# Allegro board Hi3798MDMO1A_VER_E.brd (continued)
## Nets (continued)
NF_DQ1_EMMC_D1: R12.2 U1.R22 U19.30 U22.H4
NF_DQ2_EMMC_D2: R29.2 U1.R21 U19.31 U22.H5
NF_DQ3_EMMC_D3: R58.2 U1.T21 U19.32 U22.J2
NF_DQ4_EMMC_D4: R176.2 U1.T20 U19.41 U22.J3
NF_DQ5_EMMC_D5: R177.2 U1.U22 U19.42 U22.J4
NF_DQ6_EMMC_D6: R188.2 U1.U23 U19.43 U22.J5
NF_DQ7_EMMC_D7_BOOT_SEL0: R82.1 R202.2 U1.U21 U19.44 U22.J6
NF_RDY0_EMMC_RST: C115.1 R203.2 U1.M21 U19.7 U22.U5
NF_REN_EMMC_CLK: R65.1 U19.8 U22.W6
NF_WEN_EMMC_DET: R56.2 U1.P21 U19.18
NF_WP: R89.1 R215.2 U19.19
PWR_OFF/ON: R44.1 R51.1 U1.J23
RECOVERY: C42.2 R47.2 S1.2 U1.J22
RF0: C64.1 L1.2 U7.3
RF1: C50.1 L7.2 U2.7 U7.2
RFF0: C61.1 J5.1 L1.1
RFF1: C60.1 J4.1 L7.1
RX+_PHY0: R63.1 U1.D5 U8.3 U8.6
RX-_PHY0: R64.1 U1.C5 U8.4 U8.5
SDIO0_CARD_DETECT: J21.9 R155.2 U1.F1
SDIO0_CCLK_OUT: J21.5 R5.1
SDIO0_CCMD: J21.3 R153.2 U1.E2
SDIO0_CDATA0: J21.7 R152.2 U1.D3
SDIO0_CDATA1: J21.8 R151.2 U1.C2
SDIO0_CDATA2: J21.1 R156.2 U1.F2
SDIO0_CDATA3: J21.2 R154.2 U1.E1
SDIO0_CWPR: R25.2 U1.C1
SDIO0_PWREN: R76.1 R149.1 U1.F3
SDIO_3318: C22.2 R151.1 R152.1 R153.1 R154.1 R156.1 U1.G5
SPDIF_OUT_BOOT_SEL1: R83.1 U1.A20
STANDBY_PWROFF: R35.1 R73.1 R81.1 R88.1 R98.1 U1.AB23
TX+_PHY0: R59.1 U1.B4 U8.1 U8.8
TX-_PHY0: R62.1 U1.A4 U8.2 U8.7
UART0_RXD: J18.2 R136.2 U1.AA22
UART0_TXD: J18.3 R135.2 U1.AA23
USB0_DM: C95.1 D6.1 J12.2 U1.A6
USB0_DP: C92.1 D1.1 J12.3 U1.B6
USB01_1V1: C334.1 C336.1 LB31.2 U1.G11
USB01_3V3: C10.1 C182.1 LB20.2 U1.D7
USB1_DM: J2.4 U1.B7 U2.4 U7.7
USB1_DP: J2.3 U1.C7 U2.2 U7.6
USB3_DM: J13.2 U1.AC18
USB3_DP: J13.3 U1.AB18
USB3_RXN: J13.5 U1.AB20
USB3_RXP: J13.6 U1.AC20
USB3_TXN: C77.2 U1.AA19
USB3_TXP: C81.2 U1.Y19
USB_BOOT: C89.1 R40.1 S2.1 S2.2
VDAC_3V3: C9.1 C85.1 LB14.2 U1.E20 U1.F19 U1.G19
XIN: C364.1 R1.2 U1.W23 X2.1
XOUT: R1.1 R14.1 U1.W22
$4N774: C43.1 C71.1 R7.2 R21.1
$4N775: C76.1 R53.1 R70.1 R99.2 U11.6
$4N777: L2.1 U11.3
$4N782: C8.1 R73.2 U11.1
$4N811: C82.1 R13.2 R101.1 R110.1 U13.6
$4N812: C45.1 C72.1 R23.1 R102.2
$4N813: R102.1 R110.2
$4N814: L3.1 U13.3
$4N818: C5.1 R81.2 U13.1
$4N881: C84.1 R10.1 R52.1 U15.5
$4N882: L4.1 U15.3
$4N883: C30.1 R6.2 R35.2 U15.1
$4N953: R100.1 R105.1 U14.5
$4N955: D4.1 R95.1 U14.1
$4N956: C83.2 R104.1
$4N957: C24.1 C83.1 U14.6
$4N958: R4.2 U14.7
$4N975: C44.1 U14.8
$4N980: C65.1 R95.2
$4N983: C65.2 L5.1 U14.3
$4N998: R7.1 R70.2
$5N541: Q4.3 R118.2 R144.2
$5N542: C6.2 Q13.1 Q14.1 R118.1
$5N549: Q4.1 R98.2
$6N188: C365.1 R14.2 X2.3
$6N1407: R173.1 U1.E6
$6N2001: R61.2 U1.Y17
$6N2177: R43.1 R85.1 U1.L19
$6N2315: R5.2 U1.E3
$6N2392: R65.2 U1.N23
$7N1408: C250.2 U1.G17
$7N1630: R40.2 U1.H21
$7N1639: R18.2 R87.2 U1.D8
$7N1763: R32.2 U1.F20
$8N1506: R45.1 U1.W16
$8N1514: R36.2 U1.AA7
$8N1515: R37.2 U1.AB7
$9N2352: C255.2 U1.T19
$11N1282: R46.2 U3.L8
$12N1565: R71.2 U6.L8
$13N604: C123.1 C124.1 U22.K2
$13N728: R68.1 U19.39
$13N772: R80.2 U19.38
$14N447: R15.1 U10.3
$14N448: R41.2 U10.4
$14N488: C29.1 C52.1 J12.1 LB2.1 U10.5
$14N520: R11.1 U12.3
$14N521: R42.2 U12.4
$14N524: C38.1 C75.1 J13.1 LB3.1 U12.5
$14N708: C77.1 J13.8
$14N709: C81.1 J13.9
$15N771: C47.1 C177.1 D3.3 R178.1
$15N777: C73.2 Q15.1 R77.2 R267.1
$15N781: Q5.1 R76.2
$15N783: Q5.3 R267.2
$15N941: Q2.1 R31.2
$15N943: Q1.1 R22.2
$15N992: LED1.3 Q1.3 R2.2
$15N993: LED1.1 Q2.3 R34.2
$16N996: C363.1 R66.1 R90.2 R229.1 U5.5
$16N997: C33.2 U5.6
$16N998: C32.1 U5.7
$16N999: C32.2 U5.8
$16N1080: R49.2 R57.1 R91.2
$16N1087: C351.2 R193.1
$16N1088: C55.1 R27.2 U5.2
$16N1091: C317.1 R19.1 R27.1 R193.2
$16N1106: C55.2 R19.2 R74.2 R146.1 U5.3
$16N1113: C350.1 R194.2
$16N1114: C316.1 R20.2 R28.2 R194.1
$16N1117: C54.2 R28.1 U5.13
$16N1132: C54.1 R20.1 R72.1 R145.1 U5.12
$16N1141: R49.1 U5.11
$17N163: C154.1 C297.1 T2.7
$17N165: J25.9 R67.1
$17N167: R59.2 T2.1
$17N168: R63.2 T2.6
$17N169: R62.2 T2.3
$17N170: J25.11 R79.1
$17N171: J25.7 J25.8 R270.2
$17N172: R271.2 T2.15
$17N173: R269.2 T2.10
$17N175: J25.6 T2.9
$17N176: J25.3 T2.11
$17N177: C23.1 R269.1 R270.1 R271.1 R272.1
$17N178: J25.1 T2.16
$17N179: J25.2 T2.14
$17N180: J25.4 J25.5 R272.2
$17N182: R64.2 T2.8
$17N184: C153.1 C307.1 T2.2
$19N506: D19.1 R268.1

Pads without a net: ID1 1; ID2 1; ID3 1; ID4 1; ID5 1; ID6 1; J2 1 6 8 11; J26 14; J34 6; M20 1; M21 1; M22 1; M23 1; T2 4 5 12 13; U1 A8 A9 A11 A12 AA21 AB8 AC8 B9 B11 B12 C9 C10 C11 C12 G21 J21 K20 K21 L22 L23 Y22; U2 3; U3 J1 J9 L1 L9; U6 J1 J9 L1 L9; U7 4 9 10; U11 5; U13 5; U19 3 4 5 6 10 11 14 15 20 21 22 26 27 28 33 35 40 45 46 47; U22 1 2 A4 A6 A9 A11 AA1 AA2 AA7 AA8 AA9 AA10 AA11 AA12 AA13 AA14 AE1 AE14 AG2 AG13 AH4 AH6 AH9 AH11 B2 B13 D1 D14 H1 H2 H6 H7 H8 H9 H10 H11 H12 H13 H14 J1 J7 J8 J9 J10 J11 J12 J13 J14 K1 K3 K5 K7 K8 K9 K10 K11 K12 K13 K14 L1 L2 L3 L4 L12 L13 L14 M1 M2 M3 M5 M8 M9 M10 M12 M13 M14 N1 N2 N3 N10 N12 N13 N14 P1 P2 P3 P10 P12 P13 P14 R1 R2 R3 R5 R12 R13 R14 T1 T2 T3 T5 T12 T13 T14 U1 U2 U3 U6 U7 U10 U12 U13 U14 V1 V2 V3 V12 V13 V14 W1 W2 W3 W7 W8 W9 W10 W11 W12 W13 W14 Y1 Y3 Y6 Y7 Y8 Y9 Y10 Y11 Y12 Y13 Y14

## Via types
v1: diameter 0.508, hole 0.254, TOP to BOTTOM, 880 vias
v2: diameter 0.457, hole 0.203, TOP to BOTTOM, 450 vias

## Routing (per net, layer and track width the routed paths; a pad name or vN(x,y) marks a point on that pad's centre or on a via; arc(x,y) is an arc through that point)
1V1_CORE: length 12.3
  TOP w0.508: v1(70.2,10.33) R101.2 C82.2
  BOTTOM w0.381: 66.67,19.15 66.18,18.66 66.18,16.31 67.38,15.11 67.38,13.36 69.45,11.29 69.45,11.09 v1(70.2,10.33)
  vias: v1(66.74,21.13) v1(66.74,20.42) v1(66.74,19.71) v1(67.47,21.13) v1(67.47,20.42) v1(67.47,19.71) v1(68.23,21.13) v1(68.23,20.42) v1(68.23,19.71) v2(57.12,38.2) v2(57.12,37.4) v2(57.12,36.6) v2(57.92,37.4) v2(57.92,36.6) v2(58.72,37.4) v2(59.52,39.82) v2(59.52,37.4) v2(60.32,39.8) v2(60.32,39) v2(60.32,37.4) v2(62.56,33.31) v2(62.56,32.73) v2(63.14,33.31) v2(63.14,32.73) v2(63.72,33.31) v2(63.72,32.73) v2(67.12,28.32) v2(67.88,28.7) v2(67.85,27.76)
1V1_CPU: length 11.4
  TOP w0.381: v2(69.69,49.66) 69.69,46.65 70.37,45.97 70.37,44.03 70.62,43.77 70.94,43.77 ; v1(69.99,52.01) 69.99,52.85 R53.2 C76.2
  BOTTOM w0.381: v2(69.69,49.66) 69.69,51.72 v1(69.99,52.01)
  vias: v1(69.76,39.39) v1(69.76,38.65) v1(70.67,39.39) v1(70.67,38.65) v1(71.61,39.39) v1(71.61,38.65) v1(72.55,39.39) v1(72.55,38.65) v2(61.92,40.6) v2(61.92,39) v2(61.92,38.2) v2(62.72,40.6) v2(62.72,39.8) v2(62.72,39) v2(62.72,38.2)
1V5_DDR3: length 63.7
  TOP w0.254: U3.K2 v2(36.52,44.65) ; U3.N1 v2(34.12,44.65) ; U3.R1 v2(32.52,44.65) ; U6.K2 v2(37.32,27.44)
  TOP w0.305: U6.R1 v2(32.92,29.19) ; U3.N9 v2(34.52,38.03) ; U6.C1 v2(42.52,29.19) ; U3.H2 v2(38.11,43.85) ; U6.D2 v2(42.1,27.46) ; U3.K8 v2(36.52,39.05) ; U3.R9 v2(32.92,38.1) ; U6.E9 v2(40.92,21.69) ; U3.F1 v2(40.12,45.63) ; U6.A8 v2(44.69,23.04) ; U3.D9 v2(42.12,38.25) ; U6.G7 v2(39.72,24.25) ; U6.F1 40.12,28.64 v2(40.12,29.19) ; U6.H9 38.52,21.73 38.51,21.72 v2(38.47,21.72) ; U3.D2 v2(41.31,43.85) ; U3.B2 v2(43.72,44.66) ; U6.A1 44.12,28.64 v2(44.12,29.19) ; U6.C9 v2(42.52,21.69) ; U6.R9 v2(32.92,21.69) ; U6.H2 v2(38.9,28.23) ; U6.D9 v2(41.72,21.69) ; U3.A1 v2(44.52,45.46) ; U3.C9 v2(42.92,38.25) ; U6.N9 v2(34.52,21.69) ; U3.G7 v2(39.72,40.65) ; U6.K8 v2(36.51,22.64) ; U6.N1 v2(34.52,29.19) ; U3.E9 v2(41.32,38.25) ; U3.C1 v2(42.52,45.6) ; U3.A8 v2(43.72,39.05) ; U3.H9 v2(38.52,38.11) ; U6.B2 v2(43.7,27.46)
  TOP w0.381: R92.1 C66.1 35.73,18.65 v2(35.49,18.88) ; R33.1 C49.1 35.14,34.88 v2(34.91,35.11) ; v1(26.2,39.8) 24.04,37.64 17.2,37.64 C84.2 R10.2
  BOTTOM w0.305: v2(40.92,21.69) 40.71,21.9 C240.1 ; R24.2 v2(58.77,27.79) ; C213.1 34.52,37.51 v2(34.52,38.03) ; v2(38.47,21.72) 39,22.26 C225.1 ; C239.1 41.95,21.93 v2(41.72,21.69) ; C212.1 36.54,39.08 v2(36.52,39.05) ; C229.1 37.33,27.43 v2(37.32,27.44) ; v2(32.92,38.1) 32.92,37.51 C216.1 ; C231.1 42.86,22.04 v2(42.52,21.69) ; C238.1 44.57,22.92 v2(44.69,23.04)
  BOTTOM w0.381: C220.1 42,38.14 v2(42.12,38.25) ; v2(32.92,29.19) 32.92,29.82 C233.1 ; v2(34.12,44.65) 34.28,44.81 C214.1 ; C202.1 44.62,45.55 v2(44.52,45.46) ; C205.1 43.08,44.66 v2(43.72,44.66) ; v2(36.51,22.64) 36.74,22.4 C226.1 ; v2(41.31,43.85) 41.92,44.46 C204.1 ; v2(41.32,38.25) 41.11,38.05 C221.1 ; C230.1 34.52,29.78 v2(34.52,29.19) ; R78.1 v2(40.1,33.05) ; v2(36.52,44.65) 36.13,44.27 C201.1 ; v2(43.7,27.46) 43.57,27.59 C236.1 ; C223.1 v2(40.1,32.16) ; C211.1 v2(39.72,40.65) ; C219.1 42.89,38.23 v2(42.92,38.25) ; v2(40.12,45.63) 40.12,45.39 C209.1 ; C227.1 34.52,21.11 v2(34.52,21.69) ; v2(42.52,45.6) 42.92,46 C203.1 ; C218.1 44.06,39.39 v2(43.72,39.05) ; C215.1 32.58,44.71 v2(32.52,44.65) ; C234.1 42.71,29 v2(42.52,29.19) ; C237.1 41.94,27.62 v2(42.1,27.46) ; C208.1 v2(37.91,47.45) ; C232.1 38.93,28.2 v2(38.9,28.23) ; C258.1 39.17,24.25 v2(39.72,24.25) ; C228.1 32.92,21.12 v2(32.92,21.69) ; C210.1 38.62,43.34 v2(38.11,43.85) ; v2(44.12,29.19) 44.41,28.89 C235.1 ; R54.1 v2(37.02,47.45) ; v2(38.52,38.11) 38.58,38.04 C206.1
  vias: v1(26.2,41.83) v1(26.2,40.81) v1(26.96,41.83) v1(26.96,40.81) v1(26.96,39.8) v2(38.96,26.04) v2(38.96,25.32) v2(39.59,41.59) v2(40.48,41.59) v2(52.32,31.8) v2(53.12,33.4) v2(53.12,32.6) v2(53.12,31.8) v2(53.92,39.8) v2(53.92,39) v2(53.92,34.2) v2(53.92,31.8) v2(54.06,37.71) v2(54.03,36.47) v2(56.32,34.2) v2(56.32,33.4) v2(58.72,33.4) v2(59.52,33.4)
3V3: length 49
  TOP w0.305: U1.V20 v2(65.12,32.6) U1.W20
  TOP w0.381: R6.1 v1(17.43,39.29) ; v1(79.89,6.02) R135.1 79.89,3.89 79.93,3.86 J18.4 ; R136.1 v1(81.67,6.02)
  TOP w0.508: v1(66.9,60.83) 68.17,62.1 v1(68.93,62.1)
  BOTTOM w0.381: R60.1 69.45,7.64 ; C53.1 75,50.01 v1(75.15,50.16) ; C114.1 17.18,44.88 17.18,39.54 v1(17.43,39.29) ; v1(66.01,11.3) 66.25,11.06 R3.1 ; R105.2 v1(66.9,60.83)
  BOTTOM w0.508: 71.31,8.81 71.74,9.24 71.74,11.57 72.61,12.45 72.61,14.1 70.54,16.16 70.54,19.15 71.33,19.93 71.33,25.4 70.8,25.93 68.13,25.93 67.27,26.79 65.49,26.79 65.29,27 R88.2 65.29,27.96 65.59,28.27 66,28.27 66.28,28.55 66.28,31.16 66.25,31.19
  vias: v1(15.17,46.38) v1(15.17,45.61) v1(15.17,44.85) v1(15.93,46.38) v1(15.93,45.61) v1(15.93,44.85) v1(66.77,11.3) v1(67.53,11.3) v1(67.91,11.94) v1(68.29,11.3) v1(68.93,62.87) v1(69.82,62.87) v1(69.82,62.1) v1(70.27,8.43) v1(70.27,7.54) v1(70.71,62.87) v1(71.03,8.43) v1(71.03,7.54) v1(75.15,50.93) v1(75.15,49.4) v1(75.91,50.93) v1(75.91,50.16) v1(75.91,49.4) v1(84.62,56.56) v1(84.62,55.55) v1(84.62,54.53) v1(85.89,56.56) v1(85.89,55.55) v1(85.89,54.53)
3V3_MOS: length 55.1
  TOP w0.254: v2(58.71,43.79) 58.71,43.81 U1.D12
  TOP w0.305: R44.2 69.6,42.46 v1(70.2,43.06) ; R47.1 v1(69.06,75.82)
  TOP w0.381: v1(51.49,67.04) D19.2 ; v1(63.1,50.52) 64.14,49.47 R83.2 ; J25.12 35.66,76.8 36.38,76.08 36.38,64.53 36.64,64.27 R30.1 37.09,63.79 35.85,62.55 v1(35.85,61.77) ; D9.2 v1(67.29,71.92) ; v1(20.86,63.93) R26.1 21.24,64.7 21.62,65.09 21.62,67.99 20.99,68.63 20.99,75.25 22.55,76.8 J25.10
  BOTTOM w0.254: v1(70.39,25.29) 67.98,25.29 67.01,26.26 64.64,26.26 64.28,26.62 LB18.1
  BOTTOM w0.381: v1(21.3,60.37) 21.3,63.49 v1(20.86,63.93) ; v1(69.06,75.82) 69.06,73.69 v1(67.29,71.92) ; C283.1 v1(70.2,43.06)
  vias: v1(17.11,53.77) v1(17.11,53.01) v1(21.3,59.23) v1(23.28,26.72) v1(72.55,10.71) v1(72.55,9.95) v1(73.06,11.32) v1(73.82,11.32) v2(23.28,25.7) v2(24.16,26.72) v2(24.16,25.7) v2(53.12,43) v2(54.54,41.85) v2(55.13,41.85) v2(56.52,43.02) v2(58.73,43.2) v2(63.52,43) v2(63.52,42.2) v2(64.32,37.4) v2(75.79,43.94) v2(75.79,43.18) v2(76.55,43.94) v2(76.55,43.18)
3V3_MOS_FLASH: length 37
  TOP w0.203: U22.Y4 U22.AA3
  TOP w0.254: v1(92.27,45.09) 92.01,45.34 U19.1 ; U19.37 86.51,28.01 v1(86.52,28.01) ; v2(88.01,38.34) U22.W4 U22.Y4 ; 87.01,35.9 87.04,35.87 U22.N5 ; 87.01,35.9 U22.M6 ; 87.01,35.9 v2(86.97,35.94) ; U19.24 v1(80.51,47.55) ; v2(87.51,40.43) U22.AA5 ; v2(89.06,40.43) 88.51,39.89 U22.AA3 ; U22.K6 87.01,34.5 v2(86.65,34.86) 84.85,34.86 84.49,35.22 84.49,37 84.86,37.37 U22.T10 85.53,37.37 v2(85.54,37.36) 85.54,37.84 U22.U9 ; U19.34 85.01,25.36 v1(84.8,25.15) ; 86.51,45.33 U19.12
  TOP w0.381: v2(86.38,43.4) 86.51,43.53 86.51,45.33 ; v2(87.51,40.43) 87.51,41.2 87.94,41.63 88.65,41.63 89.06,41.22 v2(89.06,40.43) ; R68.2 R80.1 v1(85.82,24.15) ; R58.1 v1(81.57,24.05) ; R29.1 v1(81.57,25.07)
  BOTTOM w0.381: 87.6,44.07 91.25,44.07 v1(92.27,45.09) ; v1(80.51,47.55) 79.98,48.08 79.98,50.16 ; R215.1 84.34,42.16 86.09,42.16 86.38,42.45 C142.1
  vias: v1(77.06,50.93) v1(77.06,50.16) v1(77.82,50.93) v1(77.82,50.16)
3V3_SD:
  vias: v1(13.32,56.08) v1(13.32,55.29)
3V3_WIFI:
  vias: v1(17.31,27.48) v1(18.2,27.48)
5V0: length 14.4
  TOP w0.254: 74.64,56.39 74.64,54.23 74.14,53.72 73.25,53.72 72.23,54.74 v1(67.91,54.74)
  TOP w0.381: R144.1 74.58,18.18 v1(74.58,16.33)
  BOTTOM w0.381: R4.1 66.9,55.75 v1(67.91,54.74)
  vias: v1(73.8,14.4) v1(74.71,14.4) v1(75.47,14.4) v1(77.76,73.33) v1(77.76,71.93) v1(77.76,69.39) v1(78.19,61.06) v1(78.19,60.17) v1(78.65,73.33) v1(78.65,71.93) v1(78.65,69.39) v1(79.08,61.06) v1(79.08,60.17) v1(79.54,73.33) v1(79.54,71.93) v1(79.54,69.39) v1(79.97,61.06) v1(79.97,60.17)
5V0_MOS: length 4.1
  TOP w0.381: R15.2 v1(81.63,69.57) ; 76.52,13.61 76.29,13.84 74.36,13.84 R11.2 ; D20.2 v1(55.91,77.1)
  vias: v1(69.15,66.16) v1(69.15,65.4) v1(76.28,18.89) v1(77.25,18.89) v1(77.25,18.16) v1(77.29,17.32) v1(77.71,13.41) v1(77.71,12.7) v1(78.02,14.05) v1(81.25,74.93) v1(82.01,74.93) v1(82.77,74.93)
5V0_MOS_HDMI: length 14
  TOP w0.254: 52.46,78.17 52.22,78.41 J26.18
  TOP w0.381: U4.5 v1(54.01,73.42) 54.73,73.42 55.15,73.84 D20.1 55.15,75.1 54.53,75.73 R187.2 v1(53.78,76.49) 52.46,77.81 52.46,78.17 ; R186.2 v1(52,76.49)
  BOTTOM w0.381: v1(54.01,73.42) 53.93,73.34 C150.1 ; v1(52,76.49) v1(53.78,76.49)
AVDD11_PLL012: length 0.6
  TOP w0.305: U1.P17 v2(61.92,36.6)
AVDD11_USB3:
  vias: v2(61.92,35)
AVDD33_ADAC: length 0.6
  TOP w0.305: U1.E19 v2(64.32,43.8)
AVDD33_PLL01: length 0.6
  TOP w0.305: v2(64.3,35.8) 63.92,35.42 U1.R19
AVDD33_USB2: length 0.6
  TOP w0.305: v2(64.32,39.8) 63.92,39.4 U1.K19
AVDD33_USB3: length 5.6
  TOP w0.254: U1.W18 63.06,32.25 62.38,32.25 U1.W17
  TOP w0.305: U1.W18 v2(63.52,31.8)
  BOTTOM w0.381: LB18.2 64.28,28.99 C18.1 63.74,29.54 63.74,31.58 v2(63.52,31.8)
GND: length 521.8
  TOP w0.089: U22.Y2 89.26,39.62 90.03,39.62
  TOP w0.127: U1.L3 51.12,38.6 ; U1.G16 U1.E16 ; v2(57.92,46.2) 57.92,46.2 v2(58.72,46.2)
  TOP w0.165: U1.AB6 53.52,29.99 53.93,30.4 53.93,31.01 U1.Y7
  TOP w0.203: 62.59,43.81 63.53,43.81 U1.D19 ; U3.J8 38.11,39.85 38.11,40.55 ; U1.AB4 51.92,29.99 52.33,30.4 52.33,30.78 52.13,30.98 51.54,30.98 U1.Y3 ; 61.84,26.54 61.84,27.08 61.94,27.18 61.94,29.34 62.32,29.72 62.32,30.59 U1.AA17 62.32,30.6 v2(62.72,31) ; v2(51.52,35) 50.95,35 50.55,35.4 U1.R2 ; U1.V10 U1.W11 57.92,32.6 v2(58.72,32.6) ; U6.J8 37.72,23.24 37.33,23.63 37.33,24.18 v2(37.43,24.29) ; v2(50.72,31.8) 50.05,31.8 49.65,31.4 U1.Y1 ; v2(59.52,32.6) 60.3,32.6 ; v2(51.52,33.4) 50.9,33.4 50.5,33.8 U1.U2 ; U1.W21 65.92,31.8 66.72,31.8 U1.Y23 ; v2(60.32,31.8) 60.32,31.15 60.72,30.75 U1.AA15 ; U1.W8 55.52,32.6 v2(56.32,32.6) ; U22.AA4 U22.Y5 U22.AA6
  TOP w0.229: v2(87.47,34.86) 87.52,34.86 U22.K4
  TOP w0.254: v1(85.81,28.01) 86.01,27.8 U19.36 ; U3.T1 v2(31.72,44.65) ; v2(49.92,30.2) U1.AA2 ; v2(86.75,40.46) 87.01,40.19 U22.AA6 ; C140.2 v1(60.59,75.36) ; J26.8 v1(47.22,78.31) ; 57.59,58.46 58.66,57.4 R183.2 ; v1(70.33,46.86) v1(70.33,50.87) ; J26.11 v1(48.72,78.31) ; U19.25 80.51,27.85 v1(80.3,28.07) ; U19.2 91.53,46.4 91.53,45.23 v1(91.39,45.09) ; v1(81.27,47.55) 81.01,47.29 U19.23 ; 50.51,41.91 48.61,41.91 46.07,44.45 46.07,46.23 44.93,47.37 43.4,47.37 ; J26.17 v1(51.72,78.31) ; U6.J2 v2(37.32,28.24) ; 72.73,9.37 74.08,10.71 v1(75.73,10.71) ; v2(88.36,41.04) 88.35,41.04 88.35,40.48 88.01,40.15 U22.AA4 ; U3.J2 v2(38.12,44.65) ; U3.M1 v2(35.72,44.65) ; v1(62.77,60.95) 62.52,60.7 C316.2 ; 61.84,25.1 61.84,26.54 ; U1.Y23 67.56,31.4 v2(67.75,31.59) ; U19.48 v1(92.01,28.07) ; J26.5 v1(45.72,78.31) ; J26.2 v1(44.22,78.31) ; R149.2 v1(30.84,50.56) ; C339.2 v1(63.31,75.36) ; U3.P1 v2(33.32,44.65) ; D9.1 v1(66.33,72.94) ; 85.86,45.36 86.01,45.51 U19.13
  TOP w0.305: U1.M8 55.12,38.25 v2(55.05,38.32) ; v2(60.32,31.8) U1.W15 ; v2(50.72,30.2) 51.12,30.6 ; 51.12,30.6 v2(50.72,31) U1.Y3 v2(50.72,31.8) U1.W3 ; 51.12,30.6 U1.AA3 ; U1.K1 v2(49.01,39.4) ; R9.2 v1(69.79,70.48) C79.2 ; U6.E8 v2(41.32,23.44) U6.D8 ; v1(47.15,73.06) U24.3 U24.8 v1(47.15,76.04) ; C42.1 v1(69.06,76.83) ; U6.B9 43.32,21.81 v2(43.41,21.72) ; U1.C8 v2(55.52,45.4) U1.B8 v2(55.52,46.2) ; v2(67.52,29.4) U1.AC23 ; v2(40.12,21.69) 40.14,21.69 40.12,21.72 U6.F9 ; U1.C15 59.92,44.2 U1.D14 v2(59.52,43.8) ; U1.C15 v2(61.12,45.4) ; U1.C15 U1.D15 U1.E16 v2(61.92,43.8) U1.E17 ; v2(51.52,37.4) U1.N3 U1.N2 ; U3.B3 v2(43.72,43.86) ; U1.AB12 v2(57.92,29.4) U1.AC11 ; v2(50.72,32.6) U1.W3 ; U1.W3 v2(51.52,32.6) U1.V4 ; v2(50.87,28.45) 51.12,28.7 U1.AC3 ; v2(53.12,34.2) U1.U5 v2(52.32,33.4) U1.V4 ; 51.12,45 51.12,45 U1.C3 ; U1.P19 63.92,36.2 v2(64.32,36.6) U1.P20 ; U1.J11 57.52,40.2 v2(57.92,39.8) ; U1.V21 v2(65.12,33.4) U1.U20 ; U6.E2 v2(41.3,28.23) 40.92,28.62 U6.E1 ; U1.K5 v2(52.32,39.8) ; U3.E8 v2(41.32,39.05) ; U1.R20 64.72,35.4 v2(65.12,35) ; U1.V4 v2(51.52,33.4) ; 51.12,38.6 v2(50.72,39) U1.K3 v2(51.52,39.8) ; U3.B9 v2(42.92,39.05) ; U6.T1 v2(31.73,29.03) ; v1(45.58,73.01) v1(45.58,74.62) v1(45.58,76.08) ; v2(38.52,41.01) 38.11,40.61 38.11,40.55 ; U6.D1 v2(41.72,29.19) ; U6.G9 39.32,21.72 39.34,21.69 v2(39.29,21.69) ; U1.G3 51.12,41.8 v2(50.72,41.4) 51.12,41 v2(50.72,40.6) U1.J2 ; U1.H13 v2(58.72,41.4) U1.G12 ; v2(28.67,26.16) 29.09,26.59 C314.2 ; v2(64.32,38.2) U1.L20 ; U1.F21 65.04,42.12 U1.G20 64.72,41.8 v2(65.12,41.4) U1.H20 U1.J20 ; U1.AA15 U1.AA14 v2(59.52,30.2) U1.AA13 ; U1.T1 v2(49.01,34.6) ; U3.G9 v2(39.32,38.11) ; U6.P9 v2(33.72,21.69) ; U1.G13 v2(59.52,41.4) U1.H14 ; v2(50.72,47) U1.A3 v2(50.72,46.2) U1.B3 U1.C3 ; U6.M9 v2(35.32,21.69) ; U1.A1 49.52,46.6 v2(49.92,47) U1.A2 v2(49.92,46.2) ; v2(58.72,32.6) 58.72,32.6 U1.W13 v2(59.52,32.6) ; U1.L11 57.52,38.6 v2(57.92,38.2) ; U1.Y1 v2(49.01,31.4) ; v2(57.92,38.2) U1.M11 ; v2(57.92,38.2) U1.L12 ; v2(57.92,38.2) U1.M12 ; U6.G8 v2(39.72,23.45) ; U1.C6 53.52,45 v2(53.92,44.6) 53.52,44.2 U1.D6 ; U3.A9 v2(43.72,38.25) ; U1.D13 U1.C13 59.12,45.8 v2(58.72,46.2) ; U6.B3 v2(43.7,26.66) ; U3.M9 v2(35.32,38.1) ; U6.B1 v2(43.32,29.19) ; U1.R4 v2(51.52,35) ; U1.Y18 v2(62.72,31) U1.AA18 ; U6.G1 v2(39.32,29.61) ; U3.B1 v2(43.72,45.46) ; U1.L4 v2(52.32,38.2) ; U1.W8 55.12,32.2 v2(54.72,31.8) ; U1.D17 v2(62.72,44.6) U1.C17 ; U3.G8 v2(39.72,39.85) ; U3.G1 v2(39.32,45.63) ; C17.2 v1(70.61,75.06) ; U1.C3 U1.C4 U1.D4 51.72,44 51.72,43.6 U1.E4 ; U1.AA8 v2(55.52,31) U1.Y9 ; U1.P1 v2(49.01,36.2) ; v1(43.98,73.06) U23.3 U23.8 v1(43.98,76.09) ; U1.K11 57.52,39.4 v2(57.92,39) U1.K12 ; U3.T9 v2(32.12,38.1) ; U1.H12 58.32,41 v2(58.72,40.6) ; U3.F9 v2(40.12,38.11) ; U3.E1 40.92,45.07 v2(41.31,45.46) U3.D1 ; v2(49.92,29.4) U1.AC1 v2(49.12,28.6) ; U1.AB10 v2(56.32,30.2) ; U6.A9 v2(44.12,21.69) ; U6.P1 v2(33.72,29.19) ; v2(56.32,32.6) U1.V10 ; U3.E2 v2(41.32,44.66) ; U3.P9 v2(33.32,39.05) ; v2(57.12,31.8) U1.W11 ; U6.M1 v2(35.32,29.19) ; U1.J15 v2(61.12,40.6) 60.72,41 U1.H15 U1.G16 ; v2(49.92,30.2) U1.AB1 v2(49.12,29.4) ; U1.AA20 v2(64.32,31) U1.Y20 U1.W19 ; U1.AC5 v2(52.72,28.45) ; U1.D9 v2(55.52,43.8) ; R51.2 v2(68.87,39.12) ; U1.P5 v2(52.32,36.6) ; U1.AA17 v2(61.92,31) ; U1.AC9 v2(55.92,28.5) ; U6.T9 v2(32.12,21.69) ; U3.D8 v2(42.12,39.05)
  TOP w0.356: U5.10 v1(63.66,67.87) ; U5.14 v1(63.66,70.47) 63.11,70.47 62.49,71.09 v1(62.49,71.8) R145.2 ; U5.4 v1(60.11,68.52) ; U5.1 v1(60.11,70.47) 60.78,70.47 61.4,71.09 v1(61.4,71.8) R146.2
  TOP w0.381: R183.2 59.19,57.04 v1(59.72,56.51) ; D6.2 v1(83.49,59.82) ; v1(66.46,70.55) 66.71,70.3 R57.2 ; 89.71,51.13 J3.1 ; J3.1 92.22,51.13 ; J3.1 90.97,52.38 ; J3.1 90.97,49.87 ; C87.2 R93.2 v1(39.48,18.65) ; J21.14 v1(14.39,48.07) ; J13.4 86.4,17.77 ; C33.1 v1(55.53,66.74) ; v2(39.05,34.88) R55.2 C86.2 ; C59.2 v1(75.28,54.86) ; C363.2 v1(54.77,67.88) ; v1(65.36,7.11) 66.38,8.12 Q1.2 ; R13.1 73.69,11.98 v1(73.82,12.11) ; U11.2 v1(70.33,50.87) 70,51.2 C43.2 69.27,51.46 v1(69.27,52.37) ; C95.2 v1(82.39,59.82) ; R50.2 v1(62.9,57.4) ; R52.2 v1(13.5,38.37) ; C317.2 v1(58.33,60.7) ; v2(68.89,47.62) C72.2 ; 85.86,45.36 85.02,44.52 85.02,42.87 v2(84.92,42.77) ; C112.2 v1(75.35,66.21) ; U1.H3 51.12,41 ; C71.2 v1(67.43,52.32) ; D1.2 v1(83.49,63.91) ; R99.1 v1(74.9,53.09) ; U4.2 v1(49.28,73.42) ; C149.2 v1(54.26,70.27) ; v2(54.72,31.8) U1.Y7 ; C92.2 v1(82.39,63.91) ; R8.1 v1(54.26,71.28) ; C45.2 v1(73.08,15.54) ; v1(76.56,14.37) 76.56,14.6 Q4.2 ; R229.2 v1(56.27,72.05) ; R41.1 v1(84.3,69.57)
  TOP w0.508: v1(65.36,7.11) 65.13,6.88 v1(65.13,5.21) LED1.2 ; U11.2 72.6,50.87 v1(72.62,50.85) ; J13.10 87.35,9.58 ; J13.10 87.35,5.82 ; J13.10 85.47,7.7 ; J12.5 90.79,55.28 ; J12.5 86.88,55.28 ; J12.5 88.84,53.33 ; J12.5 88.84,57.24 ; v1(72.62,50.85) v1(72.62,51.96) ; v1(72.62,50.85) v1(72.62,49.88) ; J12.4 87.51,65.35 ; J12.4 84.74,65.35 ; J12.4 86.13,64.29 ; J12.4 86.13,66.42 ; J12.6 88.84,70.38 ; J12.6 88.84,66.47 ; J12.6 90.79,68.42 ; J12.6 86.88,68.42 ; v1(13.17,57.32) 12.85,57.64 J21.6 10.92,57.64
  TOP w0.635: J26.20 55.47,82.88 ; J26.20 54.28,80.8 ; J26.20 56.66,80.8 ; J26.20 55.47,78.72 ; 73.35,84.4 S1.1 ; S1.1 74.55,83.21 ; S1.1 75.74,84.4 ; S1.1 74.55,85.6 ; 85.58,83.7 J1.3 83.42,82.43 ; 80.72,81.25 J10.3 ; J10.3 79.39,83.18 ; J10.3 80.72,85.11 ; J34.5 66.41,77.65 ; J34.5 65.16,79.25 ; J34.5 65.16,76.05 ; 40.97,78.72 J26.21 ; J26.21 40.97,82.88 ; J26.21 39.78,80.8 ; J26.21 42.16,80.8 ; 89.49,20.84 J13.11 87.35,18.96 ; 77.3,80.2 J1.2 ; J1.2 78.62,82.36 ; J1.2 78.62,78.04 ; J1.2 79.94,80.2 ; 81.49,85.38 J10.2 ; J10.2 85.35,85.38 ; J10.2 83.42,86.71 ; S1.3 75.8,83.35 ; S1.3 77.25,81.9 ; S1.3 75.8,80.46 ; S1.3 74.35,81.9 ; 40.97,84.93 J26.23 ; J26.23 42.16,86.76 ; J26.23 39.78,86.76 ; 68.8,80.46 S1.4 ; S1.4 67.35,81.9 ; S1.4 68.8,83.35 ; 55.47,84.93 J26.22 ; J26.22 56.66,86.76 ; J26.22 54.28,86.76
  GND02 w0.635: J2.12 26.74,8.52 ; J2.12 25.75,7.53 ; J2.12 25.75,9.51 ; D3.2 72.63,3.11 ; D3.2 73.62,2.12 ; D3.2 71.64,2.12 ; D3.2 72.63,1.13 ; 87.35,5.9 J13.10 ; J13.10 87.35,9.5 ; J13.10 85.54,7.7 ; J13.10 89.15,7.7 ; 88.84,66.54 J12.6 ; J12.6 86.96,68.42 ; J12.6 88.84,70.3 ; J12.6 90.72,68.42 ; J10.3 80.72,85.03 ; J10.3 79.46,83.18 ; J10.3 80.72,81.32 ; J10.2 83.42,86.63 ; J10.2 81.57,85.38 ; J10.2 85.28,85.38 ; J12.4 87.44,65.35 ; J12.4 84.82,65.35 ; J12.4 86.13,66.34 ; J12.4 86.13,64.36 ; J3.1 90.97,52.31 ; J3.1 90.97,49.94 ; J3.1 92.15,51.13 ; J3.1 89.78,51.13 ; 87.35,19.04 J13.11 ; J13.11 89.15,20.84 ; J13.11 87.35,22.64 ; J13.11 85.54,20.84 ; S1.3 77.17,81.9 ; S1.3 75.8,83.28 ; S1.3 74.43,81.9 ; S1.3 75.8,80.53 ; 77.38,80.2 J1.2 ; J1.2 78.62,82.28 ; J1.2 78.62,78.12 ; J1.2 79.87,80.2 ; 21.76,8.52 J2.10 ; J2.10 22.75,9.51 ; J2.10 22.75,7.53 ; J2.9 17.47,9.51 ; J2.9 17.47,7.53 ; J2.9 18.46,8.52 ; 86.96,55.28 J12.5 ; J12.5 88.84,53.4 ; J12.5 90.72,55.28 ; J12.5 88.84,57.16 ; 84.83,14.27 J13.7 82.87,14.27 ; J13.4 86.33,17.77 ; J13.4 85.35,18.75 ; J13.4 85.35,16.79 ; 65.13,1 LED1.2 ; LED1.2 65.13,3.24 ; LED1.2 64.02,2.12 ; LED1.2 66.25,2.12 ; 55.47,85.01 J26.22 ; J26.22 54.35,86.76 ; J26.22 56.59,86.76 ; 83.42,82.5 J1.3 85.51,83.7 ; 68.8,80.53 S1.4 ; S1.4 67.43,81.9 ; S1.4 68.8,83.28 ; S1.4 70.17,81.9 ; J26.20 55.47,82.81 ; J26.20 55.47,78.79 ; J26.20 56.59,80.8 ; J26.20 54.35,80.8 ; J18.1 84.41,2.24 ; J18.1 83.68,3.17 ; J18.1 83.68,1.32 ; 65.16,76.13 J34.5 ; J34.5 66.33,77.65 ; J34.5 65.16,79.18 ; J26.21 40.97,82.81 ; J26.21 39.85,80.8 ; J26.21 42.09,80.8 ; J26.21 40.97,78.79 ; J2.7 14.47,9.51 ; J2.7 13.48,8.52 ; J2.7 14.47,7.53 ; 39.85,86.76 J26.23 ; J26.23 42.09,86.76 ; J26.23 40.97,85.01 ; S1.1 75.67,84.4 ; S1.1 74.55,83.29 ; S1.1 74.55,85.52 ; S1.1 73.43,84.4 ; 23.08,34.4 J2.2 23.08,36.64
  BOTTOM w0.127: 61.67,37.73 62.39,37.73 v2(62.72,37.4) ; 54.34,46.05 53.96,45.66 ; 61.83,41.09 61.45,40.71 ; 67.75,41.4 67.78,41.37
  BOTTOM w0.254: v2(65.12,41.4) 65.17,41.35 67.7,41.35 ; C53.2 74.14,51.44 ; R48.2 67.42,10.54 v1(66.96,10.08)
  BOTTOM w0.305: C238.2 43.41,21.99 v2(43.41,21.72) ; C212.2 36.54,40.64 36.17,41.01 v2(36.17,41.2) ; C229.2 37.43,25.94 v2(37.43,25.47) ; C231.2 C239.2 41.62,23.15 v2(41.32,23.44) 41.02,23.15 C240.2 40.03,23.15 v2(39.72,23.45) 39.65,23.37 C258.2 ; R61.1 63,28.77 v2(63.43,28.34) ; R71.1 v2(36.59,25.44) ; v2(36.17,41.91) 36.03,42.04 R46.1 ; C8.2 70.2,53.34 ; C225.2 39.82,21.99 v2(40.12,21.69) ; C233.2 32.88,30.77 v2(33.34,31.22) ; C313.2 31.03,44.41 31.25,44.64 31.7,44.64 v2(31.72,44.65) ; C89.2 v1(79.26,43.43)
  BOTTOM w0.381: v2(32.12,21.69) 32.12,21.14 C228.2 ; C307.2 v1(26.48,66.15) ; C236.2 43.58,26.78 v2(43.7,26.66) ; v2(55.43,39.87) 55.46,39.9 C248.2 ; v2(41.72,29.19) 41.9,29.01 C234.2 41.63,28.56 v2(41.3,28.23) ; v2(31.72,44.65) 31.76,44.7 C215.2 ; v2(34.68,19.67) 34.53,19.82 C227.2 ; C297.2 v1(30.11,66.15) ; v2(33.32,44.65) 33.47,44.8 C214.2 ; C153.2 v1(23.88,66.15) ; C224.2 40.41,26.78 v2(40.53,26.66) 40.68,26.8 C237.2 ; v2(86.75,40.46) 86.77,40.44 C323.2 ; C271.2 v2(36.13,47.45) ; C18.2 65.44,29.56 64.7,30.3 64.7,30.62 v2(64.32,31) C108.2 ; C209.2 38.95,45.26 v2(39.32,45.63) ; C218.2 44.04,38.58 v2(43.72,38.25) ; 40.3,36.62 C221.2 40.3,37.93 v2(40.12,38.11) ; 52.76,46.02 R173.2 53.3,45.49 ; C211.2 40.44,39.85 v2(39.72,39.85) ; C216.2 v2(32.93,36.1) ; C219.2 v2(42.89,36.15) ; R32.1 66.63,43.71 v2(66.72,43.8) ; C210.2 38.62,44.15 v2(38.12,44.65) ; C44.2 v1(66.9,54.74) ; C143.2 85.86,27.96 v1(85.81,28.01) ; C308.2 39.51,29.81 v2(39.32,29.61) 39.51,29.42 C232.2 ; C202.2 43.8,45.54 v2(43.72,45.46) ; C205.2 43.09,43.86 v2(43.72,43.86) ; C235.2 43.6,28.91 v2(43.32,29.19) ; v2(36.94,20.64) 36.74,20.84 C226.2 ; R75.2 v2(35.24,47.45) ; C5.2 72.35,16.28 v1(73.08,15.54) ; R104.2 65.25,56.77 v1(64.48,57.53) ; R39.2 67.27,6.96 ; C230.2 v2(34.56,31.22) ; C213.2 34.91,36.31 v2(34.91,36) ; R210.2 v1(16.83,58.11) ; C220.2 v2(42,36.15) ; C154.2 v1(32.83,66.15) ; 39.4,36.6 C206.2 39.4,38.03 v2(39.32,38.11) ; C263.2 v1(15.5,58.11) ; v2(35.72,44.65) 35.32,44.26 C201.2 ; v2(40.1,31.27) R84.2
  BOTTOM w0.508: v1(13.17,57.32) 13.18,57.34 C391.2
  vias: v1(10.96,80.69) v1(10.96,78.66) v1(10.96,68.5) v1(10.96,65.96) v1(10.96,63.42) v1(10.96,60.88) v1(10.96,35.99) v1(10.96,33.45) v1(10.96,30.91) v1(10.96,28.37) v1(10.96,8.17) v1(10.96,5.89) v1(11.08,13.25) v1(12.1,13.25) v1(12.23,81.96) v1(12.23,79.93) v1(12.23,77.39) v1(12.23,74.85) v1(12.23,72.31) v1(12.23,69.77) v1(12.23,67.23) v1(12.23,64.69) v1(12.23,44.88) v1(12.23,42.34) v1(12.23,39.8) v1(12.23,32.18) v1(12.23,29.64) v1(12.23,27.1) v1(12.23,24.56) v1(12.23,22.02) v1(12.23,19.48) v1(12.23,18.08) v1(12.23,8.17) v1(12.23,4.62) v1(13.37,14.52) v1(13.37,13.25) v1(13.37,11.98) v1(13.37,9.7) v1(13.5,71.04) v1(13.5,68.5) v1(13.5,65.96) v1(13.5,46.15) v1(13.5,43.61) v1(13.5,41.07) v1(13.5,30.91) v1(13.5,25.83) v1(13.5,23.29) v1(13.5,20.75) v1(13.5,19.48) v1(13.5,18.08) v1(13.5,16.81) v1(13.5,6.78) v1(14,83.74) v1(14.39,49.96) v1(14.39,10.08) v1(14.51,16.43) v1(14.77,69.77) v1(14.77,67.23) v1(14.77,32.18) v1(14.77,30.91) v1(14.77,29.64) v1(14.77,28.37) v1(14.77,27.1) v1(14.77,25.83) v1(14.77,22.02) v1(14.77,19.48) v1(15.15,13.76) v1(15.15,12.75) v1(15.15,10.84) v1(15.27,15.54) v1(15.91,0.81) v1(16.04,68.5) v1(16.04,65.96) v1(16.29,13.76) v1(16.29,12.75) v1(16.29,10.84) v1(16.49,41.47) v1(16.67,49.96) v1(16.67,48.05) v1(16.68,85.37) v1(16.8,15.54) v1(17.05,61.51) v1(17.05,19.48) v1(17.18,24.18) v1(17.31,67.23) v1(17.56,10.84) v1(17.75,86.49) v1(17.76,42.95) v1(17.76,41.47) v1(17.76,40.28) v1(17.81,0.81) v1(17.94,24.18) v1(17.94,14.27) v1(17.94,13.25) v1(18.32,19.48) v1(18.4,46.38) v1(18.58,65.96) v1(18.76,52.12) v1(18.7,49.96) v1(18.7,48.05) v1(18.7,11.48) v1(18.83,24.18) v1(18.83,15.54) v1(19.08,14.4) v1(19.08,9.7) v1(19.08,7.16) v1(19.08,4.62) v1(19.08,2.08) v1(19.41,46.38) v1(19.41,45.61) v1(19.41,44.85) v1(19.59,24.18) v1(19.59,18.21) v1(19.59,16.94) v1(19.59,12.37) v1(19.85,61.51) v1(19.85,22.02) v1(19.97,15.54) v1(20.35,10.84) v1(20.35,8.43) v1(20.35,0.81) v1(20.48,13.25) v1(20.86,19.48) v1(20.99,54.4) v1(20.99,53.13) v1(20.99,51.99) v1(20.99,49.96) v1(20.99,48.05) v1(20.99,41.58) v1(20.99,40.43) v1(21.37,14.27) v1(21.62,4.62) v1(21.62,2.08) v1(21.81,22.86) v1(22.01,41.58) v1(22.01,40.43) v1(22.01,39.29) v1(22.26,61.51) v1(22.19,33.15) v1(22.19,31.88) v1(22.64,10.84) v1(22.95,22.86) v1(22.95,20.7) v1(22.95,19.43) v1(22.95,14.86) v1(22.89,0.81) v1(23.02,51.99) v1(23.02,49.96) v1(23.28,60.5) v1(23.28,59.48) v1(23.53,54.4) v1(24.16,4.62) v1(24.16,2.08) v1(24.35,22.86) v1(24.35,20.7) v1(24.35,12.83) v1(25.05,61.39) v1(25.18,10.84) v1(25.37,32.11) v1(25.43,0.81) v1(26.2,51.99) v1(26.2,50.97) v1(26.38,22.86) v1(26.38,20.7) v1(26.49,32.69) v1(26.59,37.34) v1(26.7,17.32) v1(26.7,14.78) v1(26.7,9.7) v1(26.7,7.16) v1(26.7,4.62) v1(26.7,2.08) v1(27.02,30.48) v1(27.02,29.72) v1(27.02,28.96) v1(27.15,49.53) v1(27.27,38.46) v1(27.97,0.81) v1(28.26,45.64) v1(28.42,46.86) v1(29.24,14.78) v1(29.24,12.24) v1(29.24,7.16) v1(29.24,4.62) v1(29.24,2.08) v1(29.69,49.53) v1(30.51,0.81) v1(31.56,55.16) v1(31.78,12.24) v1(31.78,9.7) v1(31.78,4.62) v1(31.78,2.08) v1(32.23,52.07) v1(32.23,49.53) v1(33.05,0.81) v1(33.08,55.16) v1(34.13,64.44) v1(34.32,9.7) v1(34.32,4.62) v1(34.32,2.08) v1(34.6,55.16) v1(34.77,52.07) v1(34.77,49.53) v1(35.59,8.43) v1(35.59,0.81) v1(36.13,55.16) v1(36.86,9.7) v1(36.86,4.62) v1(36.86,2.08) v1(37.33,62.87) v1(37.31,52.07) v1(37.31,49.53) v1(37.65,55.16) v1(38.13,8.43) v1(38.13,0.81) v1(39.4,87.55) v1(39.4,85.01) v1(39.4,82.47) v1(39.4,78.28) v1(39.4,75.74) v1(39.4,73.2) v1(39.4,70.66) v1(39.4,68.12) v1(39.4,65.58) v1(39.4,63.04) v1(39.4,9.7) v1(39.4,4.62) v1(39.4,2.08) v1(39.85,52.07) v1(39.85,49.53) v1(40.67,8.43) v1(40.67,0.81) v1(41.94,75.74) v1(41.94,73.2) v1(41.94,70.66) v1(41.94,68.12) v1(41.94,65.58) v1(41.94,63.04) v1(41.94,9.7) v1(41.94,4.62) v1(41.94,2.08) v1(42.3,79.03) v1(42.39,49.53) v1(43.09,86.28) v1(43.09,83.74) v1(43.21,8.43) v1(43.21,0.81) v1(44.36,87.55) v1(44.36,85.01) v1(44.36,58.09) v1(44.33,56.31) v1(44.48,63.04) v1(44.48,9.7) v1(44.48,4.62) v1(44.48,2.08) v1(45.63,86.28) v1(45.63,83.74) v1(45.75,8.43) v1(45.75,0.81) v1(46.07,54.36) v1(46.14,56.31) v1(46.9,87.55) v1(46.9,85.01) v1(47.02,60.5) v1(47.02,9.7) v1(47.02,4.62) v1(47.02,2.08) v1(48.17,86.28) v1(48.17,83.74) v1(48.1,54.36) v1(48.1,52.32) v1(48.29,8.43) v1(48.29,0.81) v1(49.44,87.55) v1(49.44,85.01) v1(49.56,12.24) v1(49.56,9.7) v1(49.56,4.62) v1(49.56,2.08) v1(50.13,52.32) v1(50.13,50.29) v1(50.71,86.28) v1(50.71,83.74) v1(50.83,8.43) v1(50.83,0.81) v1(51.53,57.53) v1(51.98,87.55) v1(51.98,85.01) v1(52.1,14.78) v1(52.1,12.24) v1(52.1,9.7) v1(52.1,4.62) v1(52.1,2.08) v1(53.25,86.28) v1(53.25,83.74) v1(53.37,8.43) v1(53.37,0.81) v1(54.64,17.32) v1(54.64,14.78) v1(54.64,12.24) v1(54.64,9.7) v1(54.64,4.62) v1(54.64,2.08) v1(54.77,65.34) v1(54.77,62.8) v1(54.7,54.36) v1(55.91,8.43) v1(55.91,0.81) v1(56.17,60.7) v1(56.74,52.32) v1(57.06,87.55) v1(57.06,85.01) v1(57.06,82.47) v1(57.12,80.14) v1(57.18,19.86) v1(57.18,17.32) v1(57.18,14.78) v1(57.18,12.24) v1(57.18,9.7) v1(57.18,4.62) v1(57.18,2.08) v1(57.31,78.41) v1(57.31,65.34) v1(57.31,62.8) v1(57.82,75.74) v1(57.82,73.2) v1(58.45,8.43) v1(58.45,0.81) v1(58.51,85.98) v1(58.96,87.55) v1(59.72,22.4) v1(59.72,19.86) v1(59.72,17.32) v1(59.72,14.78) v1(59.72,12.24) v1(59.72,9.7) v1(59.72,4.62) v1(59.72,2.08) v1(60.55,64.38) v1(60.8,81.53) v1(60.99,23.67) v1(60.99,0.81) v1(61.56,84.45) v1(61.93,75.36) v1(62.07,80.77) v1(62.07,6.86) v1(62.2,87.38) v1(62.26,22.4) v1(62.26,19.86) v1(62.26,17.32) v1(62.26,14.78) v1(62.26,12.24) v1(62.26,9.7) v1(62.32,85.98) v1(62.32,82.3) v1(62.96,79.12) v1(63.29,25.68) v1(63.53,0.81) v1(63.98,86.87) v1(64.48,82.55) v1(64.86,80.64) v1(64.8,17.32) v1(64.8,14.78) v1(64.8,12.24) v1(65.25,83.95) v1(65.91,14.88) v1(66.07,0.81) v1(66.33,75.36) v1(66.46,82.34) v1(66.67,14.88) v1(66.95,17.02) v1(67.4,59.94) v1(67.39,59.03) v1(67.39,57.76) v1(67.39,56.49) v1(67.6,87.55) v1(67.6,85.01) v1(67.7,16.71) v1(67.75,15.92) v1(67.98,79.55) v1(67.98,77.01) v1(68.16,15.11) v1(68.16,14.24) v1(68.26,68.24) v1(68.26,67.53) v1(68.29,13.36) v1(68.42,59.94) v1(68.41,59.03) v1(68.41,57.76) v1(68.41,56.49) v1(68.61,0.81) v1(68.87,86.28) v1(69.06,13.36) v1(69.06,5.21) v1(69.2,32.76) v1(69.43,59.03) v1(69.43,57.76) v1(69.43,56.49) v1(69.6,35.48) v1(69.82,61.21) v1(69.82,13.36) v1(70.14,87.55) v1(70.27,28.11) v1(70.27,27.22) v1(70.58,13.36) v1(70.77,32.05) v1(71.15,0.81) v1(71.36,35.48) v1(71.41,86.28) v1(71.41,84.63) v1(71.41,82.09) v1(71.41,79.55) v1(71.47,60.33) v1(71.66,27.22) v1(71.99,32.76) v1(72.23,60.33) v1(72.3,73.25) v1(72.3,71.98) v1(72.3,69.31) v1(72.3,68.04) v1(72.3,65.5) v1(72.68,87.55) v1(73.04,25.25) v1(73.29,35.48) v1(73.57,73.25) v1(73.57,71.98) v1(73.57,69.31) v1(73.57,68.04) v1(73.57,65.5) v1(73.57,27.61) v1(73.64,8.3) v1(73.64,7.54) v1(73.69,0.81) v1(73.95,86.28) v1(73.95,79.55) v1(73.95,77.01) v1(74.62,25.25) v1(74.84,73.25) v1(74.84,71.98) v1(74.84,69.31) v1(74.84,68.04) v1(74.96,27.61) v1(75.09,5) v1(75.22,87.55) v1(75.28,53.85) v1(75.73,9.95) v1(75.73,9.19) v1(75.73,8.43) v1(76.06,41.35) v1(76.03,39.04) v1(76.17,20.7) v1(76.11,5) v1(76.18,32.74) v1(76.23,27.61) v1(76.23,0.81) v1(76.29,53.85) v1(76.49,86.28) v1(76.49,79.55) v1(76.49,77.01) v1(77.06,53.85) v1(77.22,41.32) v1(77.2,39.01) v1(77.76,87.55) v1(77.76,85.01) v1(77.87,22.58) v1(78.37,39.01) v1(78.77,3.35) v1(78.77,0.81) v1(79.03,86.28) v1(80.3,87.55) v1(80.3,35.1) v1(80.3,33.02) v1(80.3,30.53) v1(81.31,0.81) v1(81.57,86.28) v1(81.5,71.63) v1(81.5,70.61) v1(81.5,58.93) v1(81.63,16.89) v1(81.63,14.35) v1(82.26,55.12) v1(82.26,54.36) v1(82.26,53.59) v1(82.52,58.93) v1(82.84,87.55) v1(83.09,66.34) v1(83.15,53.59) v1(83.91,73.03) v1(84.17,53.34) v1(84.17,52.32) v1(84.47,0.89) v1(84.74,7.03) v1(84.93,73.03) v1(85.01,28.01) v1(85.31,53.34) v1(85.38,87.55) v1(85.63,68.88) v1(85.82,25.15) v1(85.95,73.03) v1(86.39,3.35) v1(86.39,0.81) v1(86.65,86.28) v1(86.65,83.74) v1(86.65,81.2) v1(86.65,78.66) v1(86.84,71.25) v1(86.96,53.34) v1(86.96,52.32) v1(87.66,2.08) v1(87.85,71.25) v1(87.92,87.55) v1(87.92,85.01) v1(87.92,83.36) v1(87.92,80.82) v1(87.92,78.28) v1(88,10.46) v1(88.87,71.25) v1(88.93,0.81) v1(89.19,86.53) v1(89.44,48.69) v1(89.88,72.01) v1(90.46,85.26) v1(90.46,83.36) v1(90.71,76.5) v1(90.71,19.48) v1(90.71,16.94) v1(90.71,14.4) v1(90.71,11.86) v1(90.71,9.32) v1(90.84,0.81) v1(91.73,84.25) v1(91.98,58.85) v1(91.98,56.31) v1(91.98,53.77) v1(91.98,48.69) v1(93,82.98) v1(93.25,76.5) v1(93.25,73.96) v1(93.25,60.12) v1(93.25,57.58) v1(93.25,55.04) v1(93.25,52.5) v1(93.25,49.96) v1(93.25,47.42) v1(93.25,44.88) v1(93.25,42.34) v1(93.25,39.8) v1(93.25,37.26) v1(93.25,34.72) v1(93.25,32.18) v1(93.25,29.64) v1(93.25,27.1) v1(93.25,22.02) v1(93.25,19.48) v1(93.25,16.94) v1(93.25,14.4) v1(93.25,11.86) v1(93.25,9.32) v1(93.25,6.78) v1(94.52,81.83) v1(94.52,80.31) v1(94.52,77.77) v1(94.52,75.23) v1(94.52,72.69) v1(94.52,70.15) v1(94.53,68.88) v1(94.52,66.47) v1(94.52,63.93) v1(94.52,61.39) v1(94.52,58.85) v1(94.52,56.31) v1(94.52,53.77) v1(94.52,51.23) v1(94.52,48.69) v1(94.52,46.15) v1(94.52,43.61) v1(94.52,41.07) v1(94.52,38.53) v1(94.52,35.99) v1(94.52,33.45) v1(94.52,30.91) v1(94.52,28.37) v1(94.52,25.83) v1(94.52,20.75) v1(94.52,18.21) v1(94.52,15.67) v1(94.52,13.13) v1(94.52,10.59) v1(94.52,8.05) v1(94.52,5.51) v1(95.07,22.81) v1(95.79,80.56) v1(95.79,79.04) v1(95.79,68.88) v1(95.79,67.74) v1(95.79,65.2) v1(95.79,62.66) v1(95.79,60.12) v1(95.79,57.58) v1(95.79,55.04) v1(95.79,52.5) v1(95.79,49.96) v1(95.79,47.42) v1(95.79,34.72) v1(95.79,32.18) v1(95.79,29.64) v1(95.79,27.1) v1(95.79,24.56) v1(95.79,22.02) v1(95.79,19.48) v1(95.79,6.78) v2(27.96,43.87) v2(29.99,44.65) v2(30.91,46.46) v2(32.23,47.5) v2(33.14,46.66) v2(41.34,41.59) v2(41.59,34.88) v2(41.59,32.34) v2(42.23,41.59) v2(42.31,25.35) v2(42.31,24.72) v2(42.64,42.8) v2(44.13,34.88) v2(45.58,38.29) v2(51.52,42.2) v2(52.32,42.2) v2(53.15,35.8) v2(53.46,40.78) v2(53.91,41.37) v2(54.25,40.78) v2(55.84,41.85) v2(56.04,39.06) v2(56.04,36.72) v2(56.1,48.9) v2(56.22,38.34) v2(56.32,42.32) v2(56.4,35.46) v2(58.72,39.8) v2(58.68,35.1) v2(58.72,34.2) v2(63.28,34.76) v2(65.12,45.4) v2(65.12,44.6) v2(65.92,45.4) v2(66.1,37.97) v2(67.04,37.97) v2(68.17,37.85) v2(68.18,41.88) v2(68.54,31.01) v2(70.21,28.85) v2(85.57,36.58) v2(86.2,35.94) v2(86.33,37.34) v2(90.01,42.8) v2(90.11,36.58) v2(90.65,41.91) v2(90.65,40.26) v2(90.62,38.61) v2(91.26,35.69) v2(91.26,34.67)
VDD_AUDIO: length 17.6
  TOP w0.356: U5.9 v1(65.95,67.22)
  TOP w0.381: R66.2 v1(55.66,69.15) ; R91.1 v1(69.27,68.93)
  BOTTOM w0.381: v1(55.66,69.15) 64.01,69.15 v1(65.95,67.22) 67.65,68.93 v1(69.27,68.93)
ADAC_VOUTL: length 15.1
  TOP w0.203: 66.72,47.2 66.72,46.2 U1.B22
  TOP w0.254: C350.2 61.31,57.44 R50.1 61.35,57.04 63.09,55.3 63.09,52.97 65.52,50.54 65.52,48.41 66.72,47.2
ADAC_VOUTR: length 14.6
  TOP w0.254: U1.A22 66.32,46.71 65.13,47.9 65.13,50.29 62.58,52.84 62.58,54.8 60,57.37 R183.1 60,57.78 60.17,57.94 C351.1
AUDIO_L: length 12.7
  TOP w0.254: R72.2 C339.1 62.49,75.91 61.31,77.09 59.78,77.09 59.02,77.85 59.02,81.71 J34.3
AUDIO_R: length 16.1
  TOP w0.254: J34.2 58.01,83.7 58.01,77.34 59.15,76.2 60.79,76.2 61.4,75.59 C140.1 R74.1
CORE_CTRL: length 4.7
  TOP w0.127: R23.2 67.7,42.29 67.7,40.89 67.42,40.61 66.71,40.61 66.71,40.61 U1.H22
CPU_CTRL: length 8.7
  TOP w0.127: U1.H23 67.12,42.22 67.95,43.05 67.95,44.88 68.16,45.08 68.16,47.87 68.64,48.35 R21.2
CVBS: length 36.2
  TOP w0.254: U1.E23 67.29,43.57 67.29,45.26 67.55,45.51 67.55,47.19 65.9,48.84 65.9,50.8 63.59,53.1 63.59,61.45 66.28,64.14 68.93,64.14 70.61,65.81 R9.1 C79.1 70.61,72.25 L6.1 70.59,73.27 C80.1
CVBS_OUT: length 16.7
  TOP w0.305: L6.2 69.79,72.28 C80.2 C17.1 69.71,74.21 D9.3 67.34,79.05 66.39,80.01 61.52,80.01 J34.4
DDR_ADDR0: length 74.7
  TOP w0.127: U1.AA12 58.71,30.21 58.71,28.77 58.01,28.07 58.01,25.89 48.63,16.51 41.5,16.51 41.12,16.13 32.53,16.13 31.46,17.2 31.46,17.94 30.06,19.34 v2(30.06,24.42) 30.36,24.42 30.69,24.74 30.69,25.25 30.87,25.43 33.52,25.43 33.92,25.84 33.92,26.34 34.52,26.93 U6.N3 ; U3.N3 34.52,43.3 33.88,42.66 33.88,42.29 33.46,41.87 30.74,41.87 30.52,41.65 30.52,41.28 v2(30.06,40.82)
  BOTTOM w0.127: v2(30.06,40.82) 29.81,40.57 29.81,35.71 30.7,34.82 30.7,33.05 29.18,31.52 29.18,27.89 30.69,26.39 30.69,25 30.11,24.42 v2(30.06,24.42)
DDR_ADDR1: length 52.4
  TOP w0.127: U3.P7 v2(34.12,39.85) ; U1.Y11 v2(57.12,31) ; U6.P7 v2(34.12,23.44)
  BOTTOM w0.127: v2(57.12,31) 57.12,30.36 56.36,29.59 56.36,28.32 47.15,19.11 35.97,19.11 35.14,19.94 35.14,21.24 34.91,21.47 34.91,21.92 34.51,22.32 34.51,22.81 34.12,23.2 v2(34.12,23.44) 34.12,24.71 35.02,25.61 35.02,27.08 33.32,28.78 33.32,29.42 33.75,29.84 33.75,31.59 34.13,31.97 34.13,35.81 33.87,36.07 33.87,38.34 34.2,38.66 34.32,38.66 34.51,38.85 34.51,39.46 v2(34.12,39.85)
DDR_ADDR2: length 78.4
  TOP w0.127: v2(30.06,41.66) 30.55,42.15 32.52,42.15 33.72,43.35 U3.P3 ; U1.W14 v2(59.52,31.8) ; v2(30.06,25.25) 30.06,25.4 30.56,25.89 32.72,25.89 33.72,26.89 U6.P3
  BOTTOM w0.127: v2(30.06,41.66) 29.43,41.03 29.43,35.59 30.32,34.7 30.32,33.86 28.42,31.95 28.42,27.56 29.81,26.16 29.81,25.5 v2(30.06,25.25) 29.64,25.25 29.2,24.81 29.2,21.37 32.95,17.61 32.95,16.54 36.16,13.34 46.53,13.34 60.36,27.16 60.36,30.96 v2(59.52,31.8)
DDR_ADDR3: length 64.3
  TOP w0.127: U6.N2 34.89,27.47 34.89,26.65 v2(34.36,26.12) ; U3.N2 34.89,43.88 34.89,43.06 v2(34.36,42.53) ; U1.AC14 59.66,28.73 59.66,26.95 48.71,16 v1(42.13,16)
  BOTTOM w0.127: v2(34.36,42.53) 34.36,40.66 32.9,39.2 32.9,38.77 33.39,38.28 33.39,35.62 33.37,35.6 33.37,32.38 31.97,30.99 31.97,29.49 32.12,29.34 32.12,28.85 34.36,26.62 v2(34.36,26.12) 33.31,25.08 33.31,19.82 37.13,16 v1(42.13,16)
DDR_ADDR4: length 55.1
  TOP w0.127: U3.P8 v2(34.12,39.05) ; U1.W12 v2(57.92,31.8) ; U6.P8 v2(34.12,22.64)
  BOTTOM w0.127: v2(57.92,31.8) 57.53,31.4 57.53,30.23 56.74,29.44 56.74,28.07 46.83,18.16 35.55,18.16 34.11,19.6 34.11,21.41 34.12,21.41 v2(34.12,22.64) 33.72,23.04 33.72,24.8 34.76,25.84 34.76,26.78 32.37,29.17 32.37,30.98 33.75,32.36 33.75,35.71 33.62,35.84 33.62,38.55 33.82,38.76 v2(34.12,39.05)
DDR_ADDR5: length 80.7
  TOP w0.127: U1.Y15 v2(61.12,31) ; U6.P2 34.1,27.46 34.1,26.89 33.47,26.26 v2(33.47,26.07) 33.06,25.66 30.72,25.66 30.46,25.4 30.46,25.09 30.23,24.86 29.86,24.86 29.64,24.63 29.64,19.06 v1(30.97,17.73) ; v2(33.37,42.42) 33.37,42.56 34.1,43.29 34.1,43.87 U3.P2
  BOTTOM w0.127: v2(33.37,42.42) 33.37,40.12 32.51,39.26 32.51,35.91 32.99,35.43 32.99,32.41 31.31,30.73 31.31,28.81 33.47,26.65 v2(33.47,26.07) ; v1(30.97,17.73) 31.05,17.64 31.05,16.28 35.52,11.81 47.16,11.81 61.91,26.56 61.91,30.21 v2(61.12,31)
DDR_ADDR6: length 56.6
  TOP w0.127: U6.R8 v2(32.52,22.64) 32.52,20.01 35.25,17.27 40.35,17.27 40.73,17.65 48.04,17.65 56.75,26.37 56.75,29.34 57.14,29.73 57.14,30.18 U1.AA10 ; U3.R8 32.52,39.05 v2(31.72,39.05)
  BOTTOM w0.127: v2(32.52,22.64) 32.52,22.8 32.12,23.19 32.12,26.98 30.65,28.45 30.65,31.04 32.23,32.61 32.23,35.23 31.34,36.12 31.34,38.48 31.72,38.86 v2(31.72,39.05)
DDR_ADDR7: length 74.6
  TOP w0.127: U3.R2 33.29,43.88 33.29,43.28 32.47,42.45 30.22,42.45 29.18,41.41 29.18,36.7 28.24,35.76 28.24,32.56 31.08,29.72 31.72,29.72 32.5,28.93 32.5,28.57 32.92,28.16 U6.R2 33.31,27.45 33.31,26.92 32.51,26.12 30.28,26.12 29.25,25.1 29.25,18.8 32.56,15.49 48.76,15.49 60.3,27.04 60.3,29.42 U1.AB14
DDR_ADDR8: length 57.4
  TOP w0.127: v2(30.89,39.1) 31.24,39.45 U3.T8 ; U6.T8 v2(31.72,22.64) 31.72,22.22 31.71,22.22 31.71,20.2 35.02,16.89 40.61,16.89 40.99,17.27 48.19,17.27 57.13,26.21 57.13,29.18 57.52,29.57 U1.AB11
  BOTTOM w0.127: v2(30.89,39.1) 30.57,38.79 30.57,35.92 31.46,35.03 31.46,32.82 29.94,31.29 29.94,28.15 31.51,26.58 31.51,24.75 31.21,24.45 31.21,23.15 v2(31.72,22.64)
DDR_ADDR9: length 82.9
  TOP w0.127: U3.R3 32.92,43.33 32.37,42.79 29.98,42.79 28.8,41.6 28.8,36.96 27.86,36.02 27.86,32.18 31.79,28.25 32.25,28.25 32.57,27.92 32.57,27.62 32.92,27.28 U6.R3 32.92,26.99 32.27,26.35 30,26.35 28.87,25.22 28.87,18.52 v1(30.52,16.88) ; U1.Y16 v2(61.92,31.8)
  BOTTOM w0.127: v1(30.52,16.88) 30.52,16.27 35.35,11.43 47.32,11.43 62.33,26.44 62.33,31.39 v2(61.92,31.8)
DDR_ADDR10: length 46.9
  TOP w0.127: U1.Y8 55.12,31.38 54.72,30.98 v2(54.72,29.4) ; U3.L7 v2(35.72,40.65) ; U6.L7 v2(35.72,24.24)
  BOTTOM w0.127: v2(35.72,40.65) 36.11,40.26 36.11,39.69 36.03,39.61 36.03,28.89 36.16,28.76 36.16,24.69 v2(35.72,24.24) 36.12,23.84 36.12,23.21 36.06,23.14 36.06,22.49 36.26,22.28 36.26,20.73 36.8,20.19 37.43,20.19 37.5,20.26 46.39,20.26 54.72,28.59 v2(54.72,29.4)
DDR_ADDR11: length 54.8
  TOP w0.127: U1.AB9 56.37,29.35 56.37,26.53 47.88,18.03 40.48,18.03 40.1,17.65 35.48,17.65 33.31,19.82 33.31,23.45 U6.R7 v2(32.52,23.44) ; U3.R7 v2(32.52,39.85)
  BOTTOM w0.127: v2(32.52,39.85) 32.22,39.56 32.22,38.86 31.72,38.35 31.72,36.22 32.61,35.33 32.61,32.51 30.98,30.89 30.98,28.63 32.52,27.09 v2(32.52,23.44)
DDR_ADDR12: length 49.9
  TOP w0.127: U6.N7 v2(34.92,23.44) ; U1.Y10 v2(56.32,31) ; U3.N7 v2(34.92,39.85)
  BOTTOM w0.127: v2(34.92,39.85) 34.92,39.63 35.35,39.2 35.35,38.69 34.91,38.26 34.91,37.88 35.35,37.45 35.35,29.85 34.91,29.42 34.91,28.51 35.55,27.87 35.55,25.18 34.92,24.55 v2(34.92,23.44) 35.31,23.05 35.31,22.27 35.73,21.85 35.73,19.99 36.23,19.49 46.89,19.49 55.47,28.07 55.47,28.96 55.91,29.4 55.91,30.35 56.32,30.75 v2(56.32,31)
DDR_ADDR13: length 79.7
  TOP w0.127: U1.AA16 61.88,30.24 61.88,29.66 61.56,29.34 61.56,27.72 47.56,13.72 32.38,13.72 28.11,17.99 28.11,25.4 28.24,25.53 28.24,26.94 28.6,27.3 30.38,27.3 30.72,26.96 32.03,26.96 U6.T3 31.73,27.43 31.34,27.43 27.1,31.67 27.1,36.53 28.03,37.47 28.03,41.95 29.53,43.45 U3.T3
DDR_ADDR14: length 58.7
  TOP w0.127: v2(57.92,30.2) 57.52,30.6 U1.AA11 ; U6.T7 v2(31.72,23.44) ; U3.T7 v2(31.72,39.85)
  BOTTOM w0.127: v2(31.72,39.85) 31.28,39.42 31.28,38.94 30.96,38.61 30.96,36.02 31.84,35.13 31.84,32.72 30.32,31.19 30.32,28.27 31.74,26.86 31.74,23.89 31.72,23.86 v2(31.72,23.44) 31.72,23.2 32.11,22.81 32.11,22.36 31.46,21.72 31.46,20.83 32.48,19.81 32.73,19.81 37.05,15.49 44.8,15.49 57.12,27.81 57.12,29.4 v2(57.92,30.2)
DDR_ADDR15: length 49.7
  TOP w0.127: U3.M7 v2(34.92,40.65) ; U6.M7 v2(35.72,23.44) ; U1.W10 v2(56.32,31.8)
  BOTTOM w0.127: v2(56.32,31.8) 55.91,31.39 55.91,30.83 55.91,30.73 55.63,30.44 55.63,29.62 55.09,29.08 55.09,28.32 46.64,19.87 36.48,19.87 35.98,20.37 35.98,22.08 35.72,22.34 v2(35.72,23.44) 35.24,23.92 35.24,24.42 35.85,25.03 35.85,28.48 35.71,28.62 35.71,39.27 35.32,39.66 35.32,40.06 34.92,40.47 v2(34.92,40.65)
DDR_BA0: length 80.3
  TOP w0.127: U3.M2 35.73,43.84 35.73,42.89 34.08,41.24 31.49,41.24 29.56,39.3 29.56,36.45 28.62,35.51 28.62,32.82 31.21,30.23 31.84,30.23 32.35,29.72 33.85,29.72 34.12,29.45 34.12,29.03 34.13,29.03 34.13,28.51 34.41,28.23 34.71,28.23 34.94,28 35.16,28 U6.M2 35.32,27.7 35.66,27.35 35.66,26.29 34.26,24.9 31.56,24.9 30.45,23.79 30.45,19.59 32.01,18.03 v1(32.01,17.36) ; U1.AC15 v2(61.12,28.6)
  BOTTOM w0.127: v1(32.01,17.36) 32.01,16.41 35.84,12.57 46.85,12.57 61.12,26.85 61.12,28.6 v2(61.12,28.6)
DDR_BA1: length 51.9
  TOP w0.127: U3.N8 v2(34.92,39.05) ; U6.N8 v2(34.92,22.64) 34.92,21.44 35.09,21.27 35.09,18.63 35.68,18.03 39.85,18.03 40.23,18.41 47.71,18.41 55.48,26.18 55.48,30.16 U1.AA9
  BOTTOM w0.127: v2(34.92,39.05) 34.92,38.79 34.54,38.42 34.35,38.42 34.12,38.19 34.12,36.28 34.51,35.89 34.51,31.79 34.12,31.41 34.12,28.69 35.27,27.54 35.27,25.38 34.52,24.63 34.52,23.21 34.92,22.82 v2(34.92,22.64)
DDR_BA2: length 73.1
  TOP w0.127: U6.M3 35.32,26.46 34.04,25.18 31.23,25.18 v2(31.08,25.03) ; v2(31.08,41.43) 31.19,41.54 33.95,41.54 35.32,42.9 U3.M3 ; U1.Y12 v2(58.72,31.8)
  BOTTOM w0.127: v2(31.08,41.43) 31.08,40.64 30.19,39.75 30.19,35.81 31.08,34.92 31.08,32.92 29.56,31.39 29.56,28.02 31.08,26.5 v2(31.08,25.03) 30.7,24.65 30.7,21.08 36.67,15.11 45.05,15.11 57.5,27.56 57.5,28.19 58.33,29.02 58.33,31.4 v2(58.72,31.8)
DDR_CASN: length 83.8
  TOP w0.127: U3.K3 v2(37.32,43.05) ; U6.K3 36.92,27.36 36.46,27.81 36.46,28.99 v2(36.81,29.34) 36.81,29.59 33.22,33.18 v2(30.24,33.18) ; U1.Y14 v2(59.52,31)
  BOTTOM w0.127: v2(59.52,31) 59.98,30.54 59.98,27.34 46.35,13.72 36.31,13.72 33.36,16.67 33.36,17.86 29.64,21.58 29.64,24.67 29.83,24.86 30.23,24.86 30.46,25.09 30.46,25.42 30.19,25.68 30.19,26.29 28.8,27.69 28.8,31.74 v2(30.24,33.18) ; v2(37.32,43.05) 37.02,42.76 37.02,41.59 37.06,41.55 37.06,41.55 37.29,41.32 37.29,41.32 37.53,41.08 37.53,37.7 37.33,37.5 37.33,31.3 37.51,31.12 37.51,30.03 v2(36.81,29.34)
DDR_CKE: length 44
  TOP w0.127: U6.K9 36.92,21.6 v2(37.4,21.12) ; U3.K9 v2(36.52,38.25) ; U1.W9 v2(55.52,31.8)
  BOTTOM w0.127: v2(55.52,31.8) 55.09,31.37 R38.2 55.09,29.96 54.95,29.82 54.52,29.82 54.2,29.49 54.2,28.7 46.61,21.12 v2(37.4,21.12) 37.4,22.33 37.01,22.73 37.01,23.73 37.01,23.74 37.01,25.6 36.62,25.99 36.62,28.86 36.31,29.17 36.31,38.05 v2(36.52,38.25)
DDR_CLK1N: length 44.9
  TOP w0.114: R37.1 52.18,24.75 46.34,18.91 40.27,18.91 37.58,21.61 37.58,21.86 37.35,22.08 37.35,23.2 36.92,23.63 U6.K7 ; v2(37.5,41.71) 37.72,41.49 37.72,41.37 37.18,40.83 37.18,40.52 U3.K7
  TOP w0.127: U6.K7 36.92,24.35 37.44,24.88 v2(37.74,24.88)
  BOTTOM w0.114: R16.2 37.85,42.16 37.85,41.97 37.59,41.71 v2(37.5,41.71) 37.86,41.35 37.86,25 v2(37.74,24.88) 37.95,24.67 37.95,24.05 37.7,23.8 37.7,23.32 R17.2
DDR_CLK1P: length 44.6
  TOP w0.114: U6.J7 38.09,23.47 38.09,22.01 37.91,21.83 37.91,21.65 38.41,21.15 38.58,21.15 38.64,21.21 38.8,21.21 38.96,21.05 38.96,20.89 38.9,20.82 38.9,20.66 39.06,20.5 39.22,20.5 39.29,20.56 39.45,20.56 39.61,20.4 39.61,20.24 39.55,20.18 39.55,20.01 40.38,19.18 46.23,19.18 52.13,25.07 R36.1 ; U3.J7 37.45,40.52 37.45,40.72 37.99,41.26 37.99,41.49 v2(38.21,41.71)
  TOP w0.127: U6.J7 37.94,24.07 37.94,24.51 38.31,24.88 v2(38.44,24.88)
  BOTTOM w0.114: R16.1 38.36,42.45 38.11,42.2 38.11,41.81 v2(38.21,41.71) 38.13,41.64 38.13,25.02 38.27,24.88 v2(38.44,24.88) 38.21,24.64 38.21,23.94 37.96,23.69 37.96,23.32 R17.1
DDR_CSN: length 72.1
  TOP w0.127: U3.L2 36.51,43.85 36.51,42.83 34.33,40.65 31.83,40.65 30.32,39.14 30.32,35.94 29.38,35 29.38,33.32 31.46,31.24 32.1,31.24 32.86,30.48 34.74,30.48 35.71,29.51 35.71,28.25 35.86,28.11 35.86,28.1 U6.L2 36.26,27.7 36.26,27.69 36.57,27.38 36.57,26.19 34.78,24.4 31.95,24.4 31.21,23.66 31.21,20.12 34.82,16.51 40.86,16.51 41.24,16.89 48.37,16.89 57.63,26.14 57.63,28.3 U1.AC12
DDR_DM0: length 13.5
  TOP w0.127: U1.K4 v2(51.52,39) ; v2(41.32,39.85) U3.E7
  BOTTOM w0.127: v2(41.32,39.85) 43.12,41.66 45.81,41.66 48.89,38.58 51.1,38.58 v2(51.52,39)
DDR_DM1: length 13.3
  TOP w0.127: U1.L5 v2(52.32,39) ; U3.D3 v2(42.12,43.85)
  BOTTOM w0.127: v2(52.32,39) 51.93,39.39 49.73,39.39 45.88,43.24 42.73,43.24 v2(42.12,43.85)
DDR_DM2: length 11.4
  TOP w0.127: U1.AA1 v2(49.12,30.2) ; U6.E7 v2(41.32,24.24)
  BOTTOM w0.127: v2(41.32,24.24) 42.63,24.24 43.91,25.53 44.45,25.53 v2(49.12,30.2)
DDR_DM3: length 11.2
  TOP w0.127: U1.Y2 v2(49.92,31) ; U6.D3 v2(42.12,26.64)
  BOTTOM w0.127: v2(42.12,26.64) 42.73,26.03 44.29,26.03 49.25,31 v2(49.92,31)
DDR_DQ0: length 16.6
  TOP w0.127: U1.H4 v2(51.52,41.4) ; U3.E3 v2(40.52,43.85)
  BOTTOM w0.127: v2(51.52,41.4) 51.28,41.4 50.87,41.8 49.78,41.8 44.85,46.74 41.62,46.74 40.91,46.02 40.91,44.25 v2(40.52,43.85)
DDR_DQ1: length 11.6
  TOP w0.127: U3.F7 40.51,39.86 40.51,38.45 41.37,37.59 43.85,37.59 44.43,37 49.52,37 U1.N1
DDR_DQ2: length 14.4
  TOP w0.127: U3.F2 40.52,44.65 40.52,45.95 41.05,46.48 44.67,46.48 45.31,45.85 45.31,44.15 48.45,41 U1.H1
DDR_DQ3: length 13.8
  TOP w0.127: U1.P3 50.72,36.6 44.14,36.6 43.66,37.08 40.59,37.08 39.72,37.95 39.72,39.06 U3.F8
DDR_DQ4: length 19.1
  TOP w0.127: U1.H5 v2(52.32,41.4) ; v2(39.72,43.85) 38.92,43.85 U3.H3
  BOTTOM w0.127: v2(39.72,43.85) 40.57,44.7 40.57,46.19 41.5,47.12 45.05,47.12 49.99,42.18 50.98,42.18 51.36,41.8 51.72,41.8 52.13,41.4 v2(52.32,41.4)
DDR_DQ5: length 15.9
  TOP w0.127: U3.H8 38.12,39.06 38.12,37.95 40.54,35.53 49.87,35.53 50.1,35.76 50.76,35.76 U1.R3
DDR_DQ6: length 16.3
  TOP w0.127: U3.G2 39.72,44.65 39.72,45.97 40.61,46.86 44.8,46.86 45.69,45.97 45.69,44.32 48.66,41.35 49.97,41.35 U1.H2
DDR_DQ7: length 14.9
  TOP w0.127: U1.P2 50.03,36.2 49.61,35.78 48.64,35.78 48.44,35.99 43.99,35.99 43.4,36.58 40.3,36.58 38.92,37.95 38.92,39.85 U3.H7
DDR_DQ8: length 12.4
  TOP w0.127: v2(42.12,39.85) U3.D7 ; U1.M4 v2(51.52,38.2)
  BOTTOM w0.127: v2(42.12,39.85) 42.12,39.86 43.54,41.27 45.56,41.27 48.64,38.2 v2(51.52,38.2)
